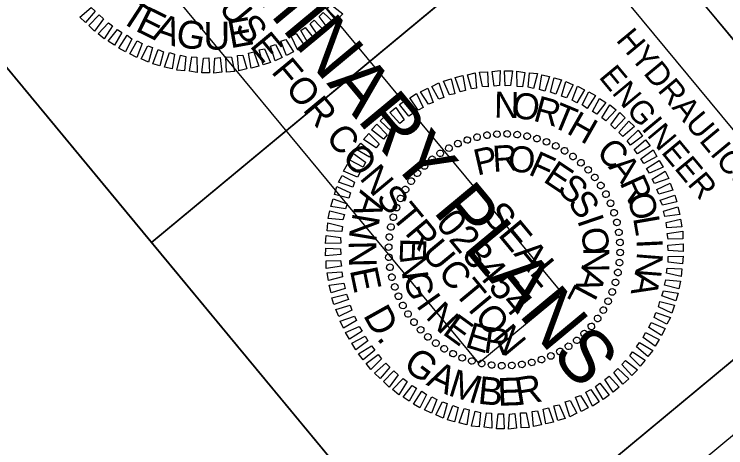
# Model space of a CAD drawing. Extents: x 2057815 to 2059783, y 687683 to 689713.
# Drawn here: x 2059495.3 to 2059649.4, y 688317.6 to 688411.4 of the extents above; entities that cross this region are included whole.
import ezdxf

# ---------------------------------------------------------------- set-up
doc = ezdxf.new("R2010")
doc.units = 0
for name, color, linetype in [('Sheet Plan CELL', 7, 'Continuous'), ('Sheet Plan Layout CELL', 7, 'Continuous'), ('Sheet Plot Border Inside CELL', 7, 'Continuous'), ('Sheet Professional Seal CELL', 7, 'Continuous'), ('Sheet Sticker Preliminary CELL', 7, 'Continuous')]:
    doc.layers.add(name, color=color, linetype=linetype)

msp = doc.modelspace()

# ---------------------------------------------------------------- linework, layer by layer
at = {"layer": 'Sheet Plan CELL'}
for p, q in [((2059557.41, 688518.82), (2059685.12, 688364.85)), ((2059557.41, 688518.82), (2059685.12, 688364.85)), ((2059611.67, 688433.83), (2059525.11, 688362.04))]:
    msp.add_line(p, q, dxfattribs=at)
for points in [[(2059704.43, 688380.81), (2058746.91, 689535.49), (2057938.66, 688865.25), (2058896.16, 687710.59)], [(2057938.66, 688865.25), (2058746.88, 689535.49), (2059576.73, 688534.83), (2059461.22, 688439.03), (2059588.9, 688285.05), (2058896.16, 687710.59)], [(2059576.73, 688534.83), (2059704.43, 688380.81), (2059685.12, 688364.85), (2059557.41, 688518.82)], [(2059547.8, 688510.85), (2059611.67, 688433.83), (2059525.06, 688362.01), (2059461.22, 688439.03)], [(2059611.67, 688433.83), (2059675.5, 688356.87), (2059588.9, 688285.05), (2059525.06, 688362.01)]]:
    msp.add_lwpolyline(points, close=True, dxfattribs=at)
at = {"layer": 'Sheet Plan Layout CELL'}
msp.add_lwpolyline([(2059388.89, 688430.01), (2059541.63, 688245.83), (2059704.44, 688380.81), (2059551.69, 688565.01)], close=True, dxfattribs=at)
at = {"layer": 'Sheet Plot Border Inside CELL'}
msp.add_lwpolyline([(2057838.75, 688981.79), (2058902.21, 687699.38), (2059714.31, 688372.8), (2058650.85, 689655.23)], close=True, dxfattribs=at)
at = {"layer": 'Sheet Professional Seal CELL'}
for p, q in [((2059599.88, 688385.46), (2059599.88, 688385.46)), ((2059602.09, 688385.53), (2059602.09, 688385.53)), ((2059604.24, 688385.37), (2059604.24, 688385.37)), ((2059593.45, 688384.21), (2059593.45, 688384.21)), ((2059595.56, 688384.79), (2059595.56, 688384.79)), ((2059597.7, 688385.27), (2059597.7, 688385.27)), ((2059606.45, 688385.06), (2059606.45, 688385.06)), ((2059608.53, 688384.51), (2059608.53, 688384.51)), ((2059589.48, 688382.42), (2059589.48, 688382.42)), ((2059591.38, 688383.41), (2059591.38, 688383.41)), ((2059610.63, 688383.78), (2059610.63, 688383.78)), ((2059612.64, 688382.92), (2059612.64, 688382.92)), ((2059587.6, 688381.31), (2059587.6, 688381.31)), ((2059614.53, 688381.89), (2059614.53, 688381.89)), ((2059585.81, 688380.02), (2059585.81, 688380.02)), ((2059616.34, 688380.65), (2059616.34, 688380.65)), ((2059618.05, 688379.22), (2059618.05, 688379.22)), ((2059584.15, 688378.58), (2059584.15, 688378.58)), ((2059619.65, 688377.75), (2059619.65, 688377.75)), ((2059582.69, 688376.98), (2059582.69, 688376.98)), ((2059581.25, 688375.27), (2059581.25, 688375.27)), ((2059621.09, 688376.09), (2059621.09, 688376.09)), ((2059580.01, 688373.46), (2059580.01, 688373.46)), ((2059622.38, 688374.3), (2059622.38, 688374.3)), ((2059578.99, 688371.57), (2059578.99, 688371.57)), ((2059623.49, 688372.42), (2059623.49, 688372.42)), ((2059624.48, 688370.52), (2059624.48, 688370.52)), ((2059578.12, 688369.56), (2059578.12, 688369.56)), ((2059625.28, 688368.46), (2059625.28, 688368.46)), ((2059577.39, 688367.46), (2059577.39, 688367.46)), ((2059576.84, 688365.38), (2059576.84, 688365.38)), ((2059625.87, 688366.34), (2059625.87, 688366.34)), ((2059626.34, 688364.2), (2059626.34, 688364.2)), ((2059576.53, 688363.17), (2059576.53, 688363.17)), ((2059576.37, 688361.02), (2059576.37, 688361.02)), ((2059626.53, 688362.02), (2059626.53, 688362.02)), ((2059601.49, 688360.42), (2059601.49, 688360.42)), ((2059626.61, 688359.81), (2059626.61, 688359.81)), ((2059576.44, 688358.81), (2059576.44, 688358.81)), ((2059626.44, 688357.66), (2059626.44, 688357.66)), ((2059576.63, 688356.63), (2059576.63, 688356.63)), ((2059626.13, 688355.45), (2059626.13, 688355.45)), ((2059577.11, 688354.49), (2059577.11, 688354.49)), ((2059625.58, 688353.37), (2059625.58, 688353.37)), ((2059577.69, 688352.37), (2059577.69, 688352.37)), ((2059578.49, 688350.31), (2059578.49, 688350.31)), ((2059624.85, 688351.27), (2059624.85, 688351.27)), ((2059579.49, 688348.41), (2059579.49, 688348.41)), ((2059623.99, 688349.26), (2059623.99, 688349.26)), ((2059622.96, 688347.37), (2059622.96, 688347.37)), ((2059580.59, 688346.53), (2059580.59, 688346.53)), ((2059621.73, 688345.57), (2059621.73, 688345.57)), ((2059581.88, 688344.74), (2059581.88, 688344.74)), ((2059620.29, 688343.85), (2059620.29, 688343.85)), ((2059583.32, 688343.08), (2059583.32, 688343.08)), ((2059618.82, 688342.25), (2059618.82, 688342.25)), ((2059584.92, 688341.61), (2059584.92, 688341.61)), ((2059617.16, 688340.81), (2059617.16, 688340.81)), ((2059586.64, 688340.18), (2059586.64, 688340.18)), ((2059615.37, 688339.52), (2059615.37, 688339.52)), ((2059588.44, 688338.94), (2059588.44, 688338.94)), ((2059590.33, 688337.91), (2059590.33, 688337.91)), ((2059613.49, 688338.41), (2059613.49, 688338.41)), ((2059592.35, 688337.05), (2059592.35, 688337.05)), ((2059594.44, 688336.32), (2059594.44, 688336.32)), ((2059607.41, 688336.04), (2059607.41, 688336.04)), ((2059609.53, 688336.62), (2059609.53, 688336.62)), ((2059611.59, 688337.42), (2059611.59, 688337.42)), ((2059596.52, 688335.77), (2059596.52, 688335.77)), ((2059598.73, 688335.46), (2059598.73, 688335.46)), ((2059600.88, 688335.3), (2059600.88, 688335.3)), ((2059603.09, 688335.37), (2059603.09, 688335.37)), ((2059605.27, 688335.56), (2059605.27, 688335.56))]:
    msp.add_line(p, q, dxfattribs=at)
for points in [[(2059563.86, 688413.51), (2059566.47, 688411.45), (2059565.26, 688410.25), (2059563.06, 688412.59)], [(2059512.84, 688412.06), (2059510.73, 688409.59), (2059509.49, 688410.77), (2059511.96, 688412.88)], [(2059562.2, 688411.74), (2059564.58, 688409.5), (2059563.34, 688408.34), (2059561.34, 688410.9)], [(2059514.6, 688410.4), (2059512.65, 688407.74), (2059511.48, 688408.92), (2059513.72, 688411.23)], [(2059560.31, 688410.11), (2059562.5, 688407.7), (2059561.19, 688406.62), (2059559.39, 688409.34)], [(2059516.56, 688408.9), (2059514.8, 688406.08), (2059513.45, 688407.17), (2059515.69, 688409.55)], [(2059558.35, 688408.55), (2059560.35, 688405.99), (2059559.02, 688405.01), (2059557.37, 688407.86)], [(2059518.59, 688407.47), (2059517.01, 688404.67), (2059515.68, 688405.58), (2059517.65, 688408.06)], [(2059556.35, 688407.21), (2059558.16, 688404.56), (2059556.72, 688403.63), (2059555.26, 688406.64)], [(2059520.77, 688406.1), (2059519.37, 688403.24), (2059517.95, 688404.02), (2059519.74, 688406.87)], [(2059522.98, 688405.07), (2059521.85, 688402.05), (2059520.32, 688402.8), (2059521.93, 688405.63)], [(2059554.13, 688405.89), (2059555.8, 688403.25), (2059554.27, 688402.44), (2059553.06, 688405.53)], [(2059525.28, 688404.18), (2059524.38, 688401.04), (2059522.77, 688401.72), (2059524.21, 688404.53)], [(2059549.54, 688403.91), (2059550.83, 688400.95), (2059549.22, 688400.46), (2059548.38, 688403.66)], [(2059551.87, 688404.86), (2059553.34, 688402.06), (2059551.85, 688401.28), (2059550.8, 688404.5)], [(2059527.64, 688403.29), (2059526.86, 688400.24), (2059525.3, 688400.63), (2059526.48, 688403.75)], [(2059530.01, 688402.78), (2059529.54, 688399.6), (2059527.87, 688399.96), (2059528.9, 688403.1)], [(2059532.48, 688402.23), (2059532.19, 688399.13), (2059530.5, 688399.29), (2059531.34, 688402.52)], [(2059544.8, 688402.57), (2059545.66, 688399.58), (2059543.98, 688399.17), (2059543.68, 688402.43)], [(2059547.21, 688403.27), (2059548.3, 688400.15), (2059546.63, 688399.74), (2059546.04, 688402.95)], [(2059534.88, 688402.08), (2059534.93, 688398.81), (2059533.25, 688399.04), (2059533.75, 688402.18)], [(2059537.46, 688401.95), (2059537.62, 688398.7), (2059535.92, 688398.72), (2059536.32, 688401.91)], [(2059539.88, 688402), (2059540.3, 688398.84), (2059538.57, 688398.65), (2059538.73, 688401.9)], [(2059542.38, 688402.13), (2059543.01, 688399.01), (2059541.29, 688398.89), (2059541.17, 688402.17)], [(2059591.93, 688394.58), (2059590.83, 688397.7), (2059592.51, 688398.11), (2059593.09, 688394.9)], [(2059594.34, 688395.28), (2059593.48, 688398.27), (2059595.15, 688398.68), (2059595.45, 688395.42)], [(2059596.76, 688395.73), (2059596.12, 688398.84), (2059597.84, 688398.96), (2059597.96, 688395.69)], [(2059599.25, 688395.85), (2059598.84, 688399.01), (2059600.56, 688399.21), (2059600.4, 688395.95)], [(2059601.67, 688395.91), (2059601.52, 688399.15), (2059603.22, 688399.14), (2059602.81, 688395.94)], [(2059604.25, 688395.77), (2059604.2, 688399.04), (2059605.89, 688398.82), (2059605.38, 688395.67)], [(2059606.65, 688395.62), (2059606.94, 688398.72), (2059608.63, 688398.56), (2059607.8, 688395.33)], [(2059609.12, 688395.07), (2059609.6, 688398.26), (2059611.27, 688397.89), (2059610.23, 688394.75)], [(2059587.27, 688392.99), (2059585.79, 688395.79), (2059587.28, 688396.58), (2059588.33, 688393.35)], [(2059589.6, 688393.94), (2059588.31, 688396.91), (2059589.92, 688397.39), (2059590.76, 688394.19)], [(2059611.49, 688394.56), (2059612.27, 688397.62), (2059613.83, 688397.22), (2059612.66, 688394.1)], [(2059613.86, 688393.67), (2059614.76, 688396.82), (2059616.36, 688396.13), (2059614.93, 688393.32)], [(2059585.01, 688391.96), (2059583.34, 688394.6), (2059584.87, 688395.42), (2059586.07, 688392.32)], [(2059616.15, 688392.78), (2059617.29, 688395.8), (2059618.82, 688395.05), (2059617.2, 688392.22)], [(2059618.37, 688391.76), (2059619.77, 688394.61), (2059621.19, 688393.84), (2059619.4, 688390.99)], [(2059582.79, 688390.64), (2059580.98, 688393.29), (2059582.41, 688394.22), (2059583.87, 688391.21)], [(2059620.55, 688390.38), (2059622.12, 688393.18), (2059623.46, 688392.28), (2059621.49, 688389.8)], [(2059580.78, 688389.3), (2059578.78, 688391.86), (2059580.12, 688392.84), (2059581.77, 688389.99)], [(2059622.58, 688388.95), (2059624.33, 688391.77), (2059625.69, 688390.68), (2059623.44, 688388.3)], [(2059578.83, 688387.74), (2059576.64, 688390.15), (2059577.94, 688391.23), (2059579.75, 688388.51)], [(2059624.53, 688387.45), (2059626.49, 688390.11), (2059627.66, 688388.94), (2059625.42, 688386.62)], [(2059576.93, 688386.11), (2059574.55, 688388.35), (2059575.8, 688389.52), (2059577.79, 688386.95)], [(2059575.28, 688384.34), (2059572.66, 688386.4), (2059573.88, 688387.6), (2059576.07, 688385.26)], [(2059626.3, 688385.8), (2059628.41, 688388.26), (2059629.65, 688387.08), (2059627.18, 688384.97)], [(2059573.72, 688382.47), (2059570.98, 688384.28), (2059572.09, 688385.6), (2059574.33, 688383.37)], [(2059628.09, 688384.03), (2059630.43, 688386.3), (2059631.44, 688385), (2059628.81, 688383.08)], [(2059629.58, 688382.15), (2059632.08, 688384.23), (2059633.1, 688382.92), (2059630.31, 688381.2)], [(2059572.25, 688380.47), (2059569.32, 688382.2), (2059570.4, 688383.49), (2059572.84, 688381.41)], [(2059570.92, 688378.32), (2059567.97, 688379.84), (2059568.81, 688381.26), (2059571.41, 688379.38)], [(2059631.06, 688380.13), (2059633.69, 688382.05), (2059634.51, 688380.59), (2059631.67, 688379.08)], [(2059632.28, 688378.03), (2059635.03, 688379.73), (2059635.89, 688378.3), (2059632.93, 688377.01)], [(2059569.68, 688376.13), (2059566.64, 688377.45), (2059567.46, 688378.97), (2059570.21, 688377.22)], [(2059568.66, 688373.99), (2059565.53, 688375.03), (2059566.31, 688376.52), (2059569.01, 688375.06)], [(2059633.49, 688375.72), (2059636.31, 688377.4), (2059637.09, 688375.84), (2059633.97, 688374.75)], [(2059634.52, 688373.45), (2059637.38, 688374.85), (2059637.99, 688373.34), (2059634.92, 688372.42)], [(2059567.8, 688371.58), (2059564.65, 688372.41), (2059565.2, 688374.1), (2059568.12, 688372.76)], [(2059635.26, 688371.15), (2059638.42, 688372.27), (2059638.85, 688370.81), (2059635.73, 688370.04)], [(2059567.05, 688369.28), (2059563.87, 688369.82), (2059564.38, 688371.48), (2059567.4, 688370.34)], [(2059566.51, 688366.88), (2059563.31, 688367.21), (2059563.68, 688368.88), (2059566.83, 688368.05)], [(2059635.97, 688368.81), (2059639.04, 688369.73), (2059639.49, 688368.09), (2059636.25, 688367.61)], [(2059636.55, 688366.3), (2059639.61, 688367.08), (2059639.91, 688365.39), (2059636.7, 688365.19)], [(2059566.24, 688364.38), (2059563.06, 688364.53), (2059563.22, 688366.22), (2059566.38, 688365.47)], [(2059636.76, 688363.94), (2059640.11, 688364.44), (2059640.13, 688362.77), (2059637, 688362.71)], [(2059566.04, 688361.88), (2059562.73, 688361.8), (2059562.89, 688363.49), (2059566.01, 688363.09)], [(2059566.06, 688359.43), (2059562.76, 688359.09), (2059562.78, 688360.8), (2059565.99, 688360.6)], [(2059636.91, 688361.41), (2059640.21, 688361.74), (2059640.19, 688360.03), (2059636.98, 688360.23)], [(2059566.22, 688356.89), (2059562.87, 688356.39), (2059562.85, 688358.06), (2059565.98, 688358.12)], [(2059636.93, 688358.95), (2059640.24, 688359.03), (2059640.08, 688357.35), (2059636.96, 688357.74)], [(2059636.73, 688356.45), (2059639.91, 688356.3), (2059639.76, 688354.61), (2059636.59, 688355.36)], [(2059566.42, 688354.53), (2059563.37, 688353.75), (2059563.06, 688355.44), (2059566.28, 688355.64)], [(2059567, 688352.02), (2059563.94, 688351.1), (2059563.49, 688352.74), (2059566.73, 688353.22)], [(2059636.46, 688353.95), (2059639.66, 688353.62), (2059639.29, 688351.95), (2059636.14, 688352.78)], [(2059635.92, 688351.56), (2059639.1, 688351.01), (2059638.59, 688349.35), (2059635.57, 688350.49)], [(2059567.71, 688349.68), (2059564.55, 688348.56), (2059564.12, 688350.02), (2059567.25, 688350.79)], [(2059568.45, 688347.38), (2059565.59, 688345.98), (2059564.98, 688347.49), (2059568.05, 688348.41)], [(2059635.17, 688349.25), (2059638.33, 688348.42), (2059637.78, 688346.73), (2059634.85, 688348.07)], [(2059634.31, 688346.84), (2059637.44, 688345.8), (2059636.66, 688344.31), (2059633.96, 688345.77)], [(2059569.48, 688345.12), (2059566.66, 688343.43), (2059565.89, 688344.99), (2059569.01, 688346.08)], [(2059570.69, 688342.8), (2059567.94, 688341.1), (2059567.08, 688342.53), (2059570.04, 688343.82)], [(2059633.29, 688344.7), (2059636.33, 688343.39), (2059635.51, 688341.86), (2059632.76, 688343.61)], [(2059632.06, 688342.51), (2059635, 688340.99), (2059634.16, 688339.58), (2059631.57, 688341.45)], [(2059571.91, 688340.7), (2059569.28, 688338.78), (2059568.46, 688340.24), (2059571.3, 688341.75)], [(2059573.39, 688338.68), (2059570.89, 688336.6), (2059569.88, 688337.91), (2059572.67, 688339.63)], [(2059630.72, 688340.36), (2059633.65, 688338.63), (2059632.57, 688337.34), (2059630.14, 688339.42)], [(2059574.89, 688336.8), (2059572.55, 688334.53), (2059571.53, 688335.83), (2059574.16, 688337.75)], [(2059629.26, 688338.36), (2059632, 688336.55), (2059630.88, 688335.23), (2059628.64, 688337.46)], [(2059627.7, 688336.49), (2059630.31, 688334.43), (2059629.1, 688333.23), (2059626.9, 688335.57)], [(2059576.68, 688335.03), (2059574.56, 688332.57), (2059573.32, 688333.75), (2059575.79, 688335.86)], [(2059626.04, 688334.72), (2059628.42, 688332.48), (2059627.18, 688331.31), (2059625.18, 688333.88)], [(2059578.44, 688333.38), (2059576.49, 688330.72), (2059575.32, 688331.89), (2059577.56, 688334.21)], [(2059624.15, 688333.09), (2059626.34, 688330.68), (2059625.03, 688329.6), (2059623.22, 688332.32)], [(2059580.39, 688331.88), (2059578.64, 688329.06), (2059577.28, 688330.15), (2059579.53, 688332.53)], [(2059622.19, 688331.53), (2059624.19, 688328.97), (2059622.85, 688327.99), (2059621.2, 688330.84)], [(2059582.43, 688330.45), (2059580.85, 688327.65), (2059579.52, 688328.55), (2059581.49, 688331.03)], [(2059620.18, 688330.19), (2059622, 688327.54), (2059620.56, 688326.61), (2059619.1, 688329.62)], [(2059584.61, 688329.07), (2059583.2, 688326.22), (2059581.78, 688326.99), (2059583.58, 688329.84)], [(2059586.82, 688328.05), (2059585.68, 688325.03), (2059584.16, 688325.78), (2059585.77, 688328.61)], [(2059617.97, 688328.87), (2059619.64, 688326.23), (2059618.1, 688325.41), (2059616.9, 688328.51)], [(2059589.11, 688327.16), (2059588.22, 688324.01), (2059586.61, 688324.7), (2059588.05, 688327.51)], [(2059613.38, 688326.89), (2059614.66, 688323.92), (2059613.05, 688323.44), (2059612.22, 688326.64)], [(2059615.7, 688327.84), (2059617.18, 688325.04), (2059615.69, 688324.26), (2059614.64, 688327.48)], [(2059591.48, 688326.27), (2059590.7, 688323.21), (2059589.14, 688323.61), (2059590.32, 688326.73)], [(2059593.85, 688325.76), (2059593.37, 688322.57), (2059591.7, 688322.94), (2059592.74, 688326.08)], [(2059596.32, 688325.21), (2059596.03, 688322.11), (2059594.34, 688322.27), (2059595.17, 688325.5)], [(2059608.64, 688325.55), (2059609.49, 688322.56), (2059607.82, 688322.15), (2059607.52, 688325.41)], [(2059611.05, 688326.25), (2059612.14, 688323.13), (2059610.47, 688322.72), (2059609.88, 688325.93)], [(2059598.72, 688325.06), (2059598.77, 688321.79), (2059597.09, 688322.01), (2059597.59, 688325.16)], [(2059601.3, 688324.92), (2059601.46, 688321.68), (2059599.75, 688321.69), (2059600.16, 688324.89)], [(2059603.72, 688324.98), (2059604.13, 688321.82), (2059602.41, 688321.62), (2059602.57, 688324.88)], [(2059606.22, 688325.1), (2059606.85, 688321.99), (2059605.13, 688321.87), (2059605.01, 688325.15)]]:
    msp.add_lwpolyline(points, close=True, dxfattribs=at)
for centre, major_axis in [((2059595.56, 688384.79), (-0.17, 0.7)), ((2059597.71, 688385.21), (-0.109, 0.712)), ((2059599.88, 688385.44), (-0.046, 0.719)), ((2059602.07, 688385.49), (0.017, 0.72)), ((2059604.25, 688385.34), (0.079, 0.716)), ((2059606.41, 688385.01), (0.141, 0.706)), ((2059591.42, 688383.39), (-0.289, 0.659)), ((2059593.46, 688384.18), (-0.23, 0.682)), ((2059608.54, 688384.48), (0.202, 0.691)), ((2059610.61, 688383.78), (0.262, 0.671)), ((2059589.46, 688382.42), (-0.345, 0.632)), ((2059612.61, 688382.89), (0.319, 0.645)), ((2059614.53, 688381.84), (0.374, 0.615)), ((2059585.82, 688380), (-0.45, 0.562)), ((2059587.58, 688381.29), (-0.399, 0.599)), ((2059616.35, 688380.62), (0.427, 0.58)), ((2059584.17, 688378.56), (-0.497, 0.521)), ((2059618.05, 688379.25), (0.476, 0.541)), ((2059582.65, 688376.98), (-0.541, 0.476)), ((2059619.63, 688377.73), (0.521, 0.497)), ((2059621.07, 688376.09), (0.562, 0.45)), ((2059581.28, 688375.27), (-0.58, 0.427)), ((2059622.36, 688374.32), (0.599, 0.399)), ((2059580.06, 688373.46), (-0.615, 0.374)), ((2059623.49, 688372.45), (0.632, 0.345)), ((2059579.01, 688371.54), (-0.645, 0.319)), ((2059578.12, 688369.54), (-0.671, 0.262)), ((2059624.46, 688370.48), (0.659, 0.289)), ((2059625.25, 688368.44), (0.682, 0.23)), ((2059577.42, 688367.47), (-0.691, 0.202)), ((2059625.86, 688366.34), (0.7, 0.17)), ((2059576.9, 688365.34), (-0.706, 0.141)), ((2059576.56, 688363.18), (-0.716, 0.079)), ((2059626.28, 688364.19), (0.712, 0.109)), ((2059626.52, 688362.02), (0.719, 0.046)), ((2059576.41, 688361), (-0.72, 0.017)), ((2059576.46, 688358.81), (-0.719, -0.046)), ((2059626.56, 688359.83), (0.72, -0.017)), ((2059626.41, 688357.65), (0.716, -0.079)), ((2059576.69, 688356.64), (-0.712, -0.109)), ((2059626.08, 688355.49), (0.706, -0.141)), ((2059577.12, 688354.49), (-0.7, -0.17)), ((2059577.73, 688352.39), (-0.682, -0.23)), ((2059625.55, 688353.36), (0.691, -0.202)), ((2059624.85, 688351.29), (0.671, -0.262)), ((2059578.52, 688350.35), (-0.659, -0.289)), ((2059623.96, 688349.29), (0.645, -0.319)), ((2059579.48, 688348.38), (-0.632, -0.345)), ((2059580.61, 688346.51), (-0.599, -0.399)), ((2059622.91, 688347.37), (0.615, -0.374)), ((2059581.9, 688344.75), (-0.562, -0.45)), ((2059621.69, 688345.56), (0.58, -0.427)), ((2059583.34, 688343.1), (-0.521, -0.497)), ((2059620.32, 688343.85), (0.541, -0.476)), ((2059584.92, 688341.58), (-0.476, -0.541)), ((2059618.8, 688342.27), (0.497, -0.521)), ((2059586.63, 688340.21), (-0.427, -0.58)), ((2059617.16, 688340.83), (0.45, -0.562)), ((2059588.44, 688338.99), (-0.374, -0.615)), ((2059613.52, 688338.41), (0.345, -0.632)), ((2059615.39, 688339.54), (0.399, -0.599)), ((2059590.36, 688337.94), (-0.319, -0.645)), ((2059592.36, 688337.05), (-0.262, -0.671)), ((2059611.55, 688337.44), (0.289, -0.659)), ((2059594.43, 688336.35), (-0.202, -0.691)), ((2059596.56, 688335.82), (-0.141, -0.706)), ((2059598.72, 688335.49), (-0.079, -0.716)), ((2059600.9, 688335.34), (-0.017, -0.72)), ((2059603.09, 688335.39), (0.046, -0.719)), ((2059605.27, 688335.62), (0.109, -0.712)), ((2059607.41, 688336.05), (0.17, -0.7)), ((2059609.51, 688336.65), (0.23, -0.682))]:
    msp.add_ellipse(centre, major_axis=major_axis, ratio=0.999708, dxfattribs=at)
at = {"layer": 'Sheet Sticker Preliminary CELL'}
msp.add_lwpolyline([(2059502.14, 688449.04), (2059520.23, 688464.04), (2059614.06, 688350.89), (2059595.97, 688335.89)], close=True, dxfattribs=at)

# ---------------------------------------------------------------- texts
at = {"layer": 'Sheet Plan CELL'}
for s, p in [('HYDRAULICS', (2059625.51, 688405.74)), ('ENGINEER', (2059621.78, 688397.76))]:
    msp.add_text(s, height=5, rotation=309.6672, dxfattribs=at).set_placement(p)
at = {"layer": 'Sheet Professional Seal CELL'}
for s, height, rotation, p in [('T', 6, 326.8409, (2059517.92, 688410.07)), ('E', 6, 333.6411, (2059521.3, 688407.93)), ('A', 6, 340.7505, (2059525.08, 688406.13)), ('G', 6, 349.5908, (2059530.04, 688404.57)), ('E', 6, 10.2542, (2059542.13, 688404)), ('U', 6, 0.3166, (2059536.29, 688403.73)), ('N', 5.64, 359.0907, (2059599.22, 688389)), ('O', 5.64, 351.8889, (2059602.92, 688389.08)), ('R', 5.64, 344.6877, (2059607.51, 688388.4)), ('T', 5.64, 337.487, (2059611.37, 688387.19)), ('H', 5.64, 330.2867, (2059614.72, 688385.74)), ('C', 5.64, 315.8871, (2059621.11, 688381.17)), ('P', 5.64, 13.0661, (2059595.6, 688376.45)), ('R', 5.64, 3.7069, (2059599.08, 688377.26)), ('O', 5.64, 354.3484, (2059602.08, 688377.47)), ('F', 5.64, 335.6342, (2059606.46, 688376.82)), ('E', 5.64, 326.2783, (2059609.66, 688375.31)), ('A', 5.64, 308.6875, (2059623.86, 688378.32)), ('S', 5.64, 316.9228, (2059612.67, 688373.33)), ('R', 5.64, 294.2883, (2059626.39, 688374.96)), ('A', 6, 251.5406, (2059570.34, 688373.55)), ('S', 5.64, 307.5676, (2059615.01, 688370.59)), ('O', 5.64, 287.0884, (2059627.95, 688371.9)), ('SEAL', 5.998, 309.6672, (2059596.52, 688367.73)), ('023454', 5.998, 309.6672, (2059586.39, 688366.07)), ('N', 6, 260.3809, (2059568.69, 688368.61)), ('I', 5.64, 288.8568, (2059617.21, 688366.83)), ('L', 5.64, 279.8881, (2059629.33, 688367.33)), ('O', 5.64, 279.5007, (2059617.95, 688364.84)), ('E', 5.64, 267.9441, (2059578.97, 688363.05)), ('I', 5.64, 272.6873, (2059630.07, 688362.68)), ('N', 6, 271.1068, (2059567.74, 688362.36)), ('N', 5.64, 270.1438, (2059618.55, 688360.99)), ('N', 5.64, 265.4861, (2059630.25, 688360.04)), ('N', 5.64, 277.3012, (2059578.81, 688359.02)), ('E', 6, 281.8326, (2059567.97, 688356.05)), ('A', 5.64, 251.4275, (2059618.37, 688357.14)), ('G', 5.64, 286.6574, (2059579.5, 688354.66)), ('A', 5.64, 258.2844, (2059629.86, 688355.88)), ('L', 5.64, 242.0681, (2059616.96, 688353.43)), ('I', 5.64, 305.3684, (2059582.22, 688348.4)), ('D', 6, 299.1423, (2059570.79, 688346.27)), ('N', 5.64, 314.7236, (2059584.24, 688345.73)), ('E', 5.64, 324.079, (2059587.86, 688342.3)), ('E', 5.64, 342.7913, (2059592.75, 688339.46)), ('R', 5.64, 352.1486, (2059596.82, 688338.23)), ('.', 6, 309.0181, (2059573.67, 688341.22)), ('G', 6, 323.2522, (2059579.24, 688334.97)), ('A', 6, 333.9781, (2059584.37, 688331.27)), ('M', 6, 342.8184, (2059589.05, 688328.99)), ('B', 6, 354.3479, (2059595.58, 688327.13)), ('R', 6, 9.1538, (2059604.28, 688326.73)), ('E', 6, 2.0445, (2059600.09, 688326.64))]:
    msp.add_text(s, height=height, rotation=rotation, dxfattribs=at).set_placement(p)
at = {"layer": 'Sheet Sticker Preliminary CELL'}
for s, height, p in [('PRELIMINARY PLANS', 11.52, (2059516.41, 688452.43)), ('DO NOT USE FOR CONSTRUCTION', 5.76, (2059518.85, 688437.43))]:
    msp.add_text(s, height=height, rotation=309.6672, dxfattribs=at).set_placement(p)

doc.saveas('drawing.dxf')
